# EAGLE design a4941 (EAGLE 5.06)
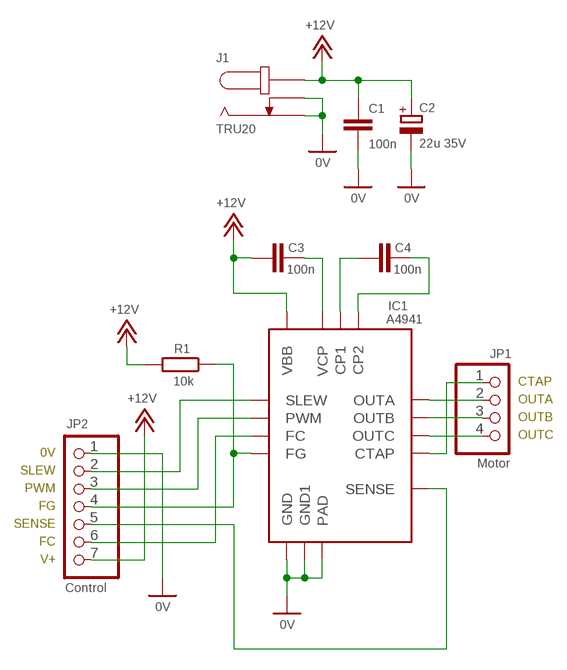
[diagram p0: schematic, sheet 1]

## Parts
C1  100n  C-EU050-024X044  [C050-024X044]
C2  22u 35V  CPOL-EUE2.5-7  [E2,5-7]
C3  100n  C-EU050-024X044  [C050-024X044]
C4  100n  C-EU050-024X044  [C050-024X044]
IC1  A4941  [TSSOP16-TP]
J1  TRU20  [TRU20]
JP1  Motor  PINHD-1X4  [1X04]
JP2  Control  PINHD-1X7  [1X07]
R1  10k  R-EU_0207/7  [0207/7]

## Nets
0V: C1.2 C2.- IC1.5(GND) IC1.11(GND1) IC1.PAD J1.2(OUTER) J1.3(SWITCH) JP2.1
+12V: C1.1 C2.+ C3.1 IC1.13(VBB) J1.4(INNER) JP2.7 R1.2
N$1: IC1.15(OUTA) JP1.2
N$2: IC1.16(OUTB) JP1.3
N$3: IC1.1(OUTC) JP1.4
N$4: IC1.12(CTAP) JP1.1
N$5: C4.1 IC1.2(CP1)
N$6: C4.2 IC1.3(CP2)
N$7: C3.2 IC1.4(VCP)
N$8: IC1.8(FG) JP2.4 R1.1
N$9: IC1.6(SLEW) JP2.2
N$10: IC1.7(PWM) JP2.3
N$11: IC1.10(FC) JP2.6
N$12: IC1.14(SENSE) JP2.5

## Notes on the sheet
- CTAP
- OUTA
- OUTB
- OUTC
- 0V
- SLEW
- PWM
- FG
- SENSE
- FC
- V+

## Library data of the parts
C1 C3 C4 = rcl:C-EU: CAPACITOR, European symbol
C2 = rcl:CPOL-EU: POLARIZED CAPACITOR, European symbol
IC1 = lindsay-motor-driver:A4941: A4941 Three-phase sensorless fan driver
J1 = lindsay-con-dcjack:TRU20: TruConnect 2.0mm dc jack socket. Rapid order code 20-0970.
JP1 = pinhead:PINHD-1X4: PIN HEADER
JP2 = pinhead:PINHD-1X7: PIN HEADER
R1 = rcl:R-EU_: RESISTOR, European symbol

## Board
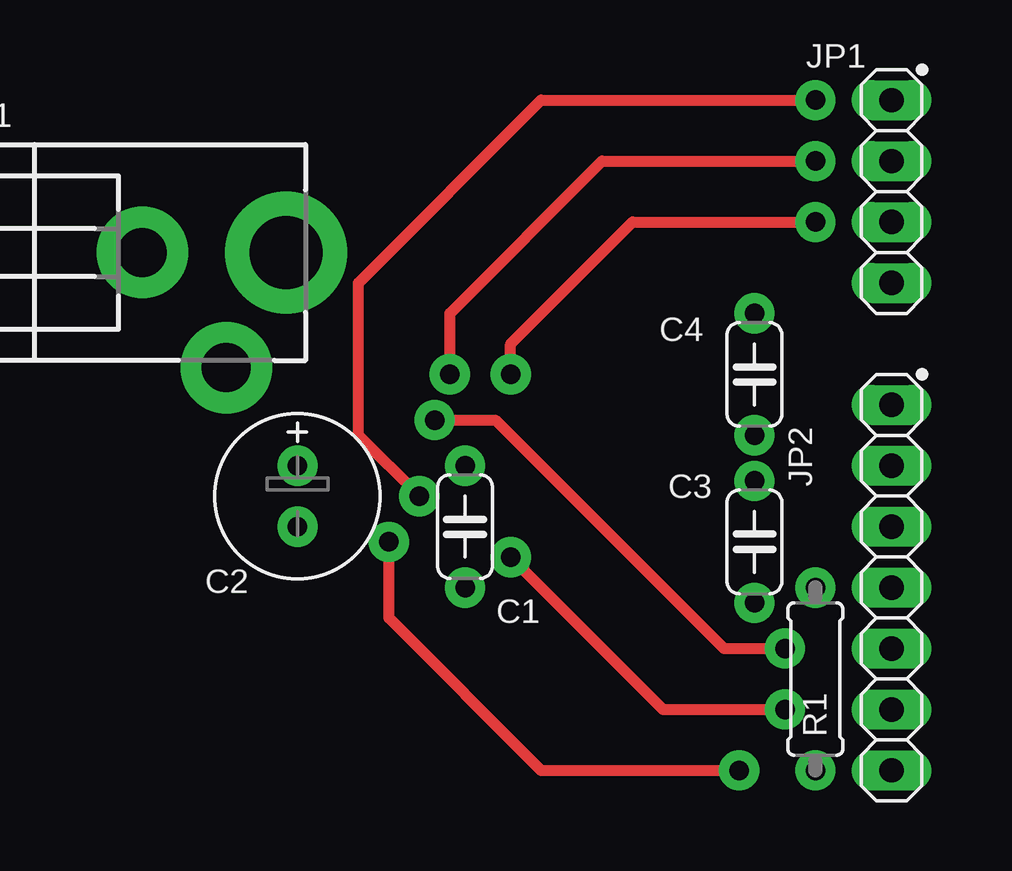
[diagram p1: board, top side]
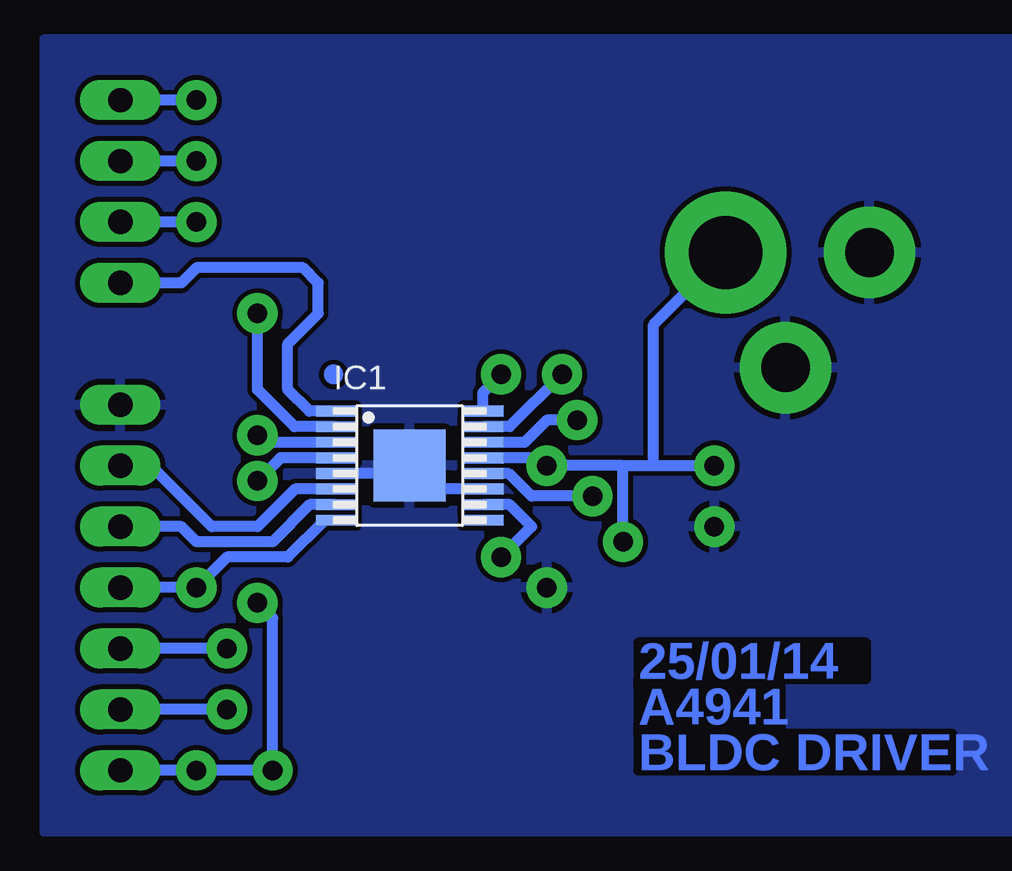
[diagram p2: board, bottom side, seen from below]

No outline drawn. Coordinates in mm, seen from the top.
Copper layers (1*16): Top 0.035mm / dielectric 1.5mm / Bottom 0.035mm
Design rules "default": minimum track width 10mil, minimum drill 24mil, track to track 8mil, track to pad 8mil, pad to pad 8mil, via to via 8mil, smd to smd 8mil, copper to edge 40mil, drill to drill 8mil, minimum pad ring 10mil, minimum via ring 8mil, stop-mask expansion 4mil, vias tented up to drill 0mil, thermal gap 10mil

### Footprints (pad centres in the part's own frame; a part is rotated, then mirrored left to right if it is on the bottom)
C050-024X044 = drill 0.813 pad 1.676 round: 1 -2.54,0; 2 2.54,0
E2,5-7 = drill 0.813 pad 1.676 round: + -1.27,0; - 1.27,0
TSSOP16-TP = smd 1.7 x 0.45: 1 -3.05,2.275; 2 -3.05,1.625; 3 -3.05,0.975; 4 -3.05,0.325; 5 -3.05,-0.325; 6 -3.05,-0.975; 7 -3.05,-1.625; 8 -3.05,-2.275; 9 3.05,-2.275; 10 3.05,-1.625; 11 3.05,-0.975; 12 3.05,-0.325; 13 3.05,0.325; 14 3.05,0.975; 15 3.05,1.625; 16 3.05,2.275 | smd 3 x 3: PAD 0,0
TRU20 = drill 2.032 pad 3.81 round: 2 11,-4.8; 3 7.5,0 | drill 3.048 pad 5.08 round: 4 13.5,0
1X04 = drill 1.016 pad 1.676 long: 1 -3.81,0; 2 -1.27,0; 3 1.27,0; 4 3.81,0
1X07 = drill 1.016 pad 1.676 long: 1 -7.62,0; 2 -5.08,0; 3 -2.54,0; 4 0,0; 5 2.54,0; 6 5.08,0; 7 7.62,0
0207/7 = drill 0.813 pad 1.676 round: 1 -3.81,0; 2 3.81,0

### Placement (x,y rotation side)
C1  20.95,12.7 270 top
C2  13.97,13.97 270 top
C3  33.02,12.06 90 top
C4  33.02,19.05 270 top
IC1  26.67,15.24 0 bottom
J1  0,24.13 0 top
JP1  38.73,26.67 270 top
JP2  38.73,10.16 270 top
R1  35.56,6.35 270 top

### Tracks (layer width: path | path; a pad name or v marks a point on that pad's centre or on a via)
0V
  Bottom 0.457: IC1.5 27,14.91 IC1.PAD 26.67,13.97 26.38,14.27 IC1.11
  pour Bottom: 0,33.02 41.91,33.02 41.91,0 0,0
+12V  (via drill 0.81 pad 1.68)
  Top 0.457: v17.78,12.06 17.78,8.89 24.13,2.54 v32.38,2.54
  Bottom 0.457: 17.78,15.24 16.51,15.24 | 16.51,15.24 C2.+ | 17.78,15.24 C1.1 21.28,15.56 IC1.13 | JP2.7 R1.2 v32.38,2.54 32.38,8.89 C3.1 | v17.78,12.06 17.78,15.24 | J1.4 16.51,21.12 16.51,15.24
N$1  (via drill 0.81 pad 1.68)
  Top 0.457: v20.32,19.05 20.32,21.59 26.67,27.94 v35.56,27.94
  Bottom 0.457: IC1.15 22.5,16.86 v20.32,19.05 | v35.56,27.94 JP1.2
N$2  (via drill 0.81 pad 1.68)
  Top 0.457: v22.86,19.05 22.86,20.32 27.94,25.4 v35.56,25.4
  Bottom 0.457: IC1.16 23.62,18.29 v22.86,19.05 | v35.56,25.4 JP1.3
N$3
  Bottom 0.457: IC1.1 30.85,17.52 31.75,18.41 31.75,20.32 30.48,21.59 30.48,22.86 31.11,23.5 35.56,23.5 36.2,22.86 JP1.4
N$4  (via drill 0.81 pad 1.68)
  Top 0.457: v19.05,13.97 16.51,16.51 16.51,22.86 24.13,30.48 v35.56,30.48
  Bottom 0.457: IC1.12 22.54,14.91 21.59,13.97 v19.05,13.97 | v35.56,30.48 JP1.1
N$5
  Bottom 0.457: IC1.2 31.47,16.86 33.02,18.41 C4.1
N$6
  Bottom 0.457: IC1.3 32.73,16.21 C4.2
N$7
  Bottom 0.457: IC1.4 32.06,15.56 C3.2
N$8
  Bottom 0.457: IC1.8 30.21,12.96 31.75,11.43 34.29,11.43 R1.1 JP2.4
N$9
  Bottom 0.457: IC1.6 31.45,14.27 33.02,12.7 34.92,12.7 37.47,15.24 JP2.2
N$10
  Bottom 0.457: IC1.7 30.84,13.62 32.38,12.06 35.56,12.06 36.2,12.7 JP2.3
N$11  (via drill 0.81 pad 1.68)
  Top 0.457: v22.86,11.43 29.21,5.08 v34.29,5.08
  Bottom 0.457: v34.29,5.08 JP2.6 | IC1.10 22.5,13.62 21.59,12.7 v22.86,11.43
N$12  (via drill 0.81 pad 1.68)
  Top 0.457: v19.68,17.14 22.23,17.14 31.75,7.62 v34.29,7.62
  Bottom 0.457: IC1.14 21.89,16.21 20.95,17.14 v19.68,17.14 | v34.29,7.62 JP2.5
(copper drawn outside any net)
  shapes: Bottom circle x1

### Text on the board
Bottom: 25/01/14 | A4941 | BLDC DRIVER
tDocu: CTAP | OUTA | OUTB | OUTC | 0V | SLEW | PWM | FG | SENSE | FC | V+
